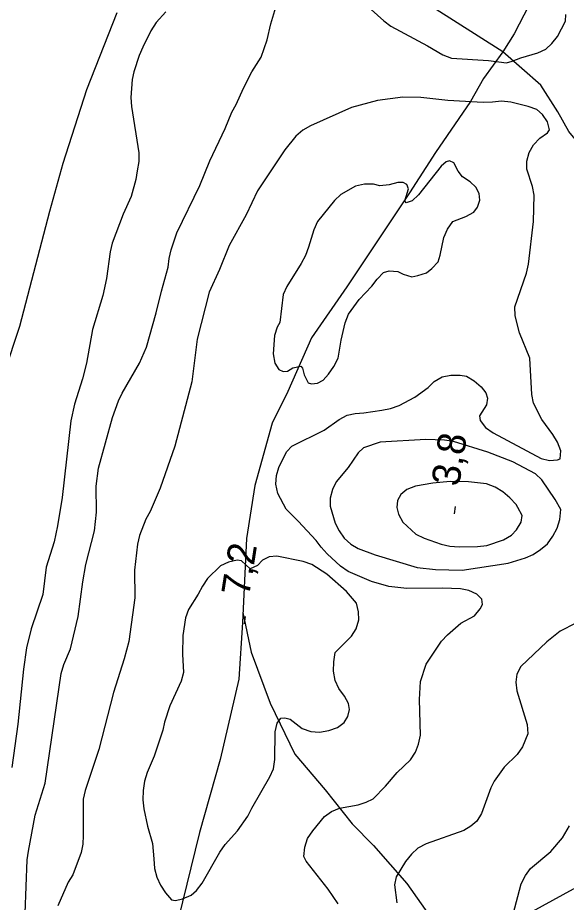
# Model space of a CAD drawing. Extents: x 282461 to 284471, y 5554090 to 5557646.
# Drawn here: x 282768 to 282826.3, y 5554895.5 to 5554989.5 of the extents above; entities that cross this region are included whole.
import ezdxf

# ---------------------------------------------------------------- set-up
doc = ezdxf.new("R2010")
doc.units = 0
for name, color, linetype in [('Niveau 1', 7, 'Continuous'), ('Niveau 2', 7, 'Continuous'), ('Niveau 22', 7, 'Continuous'), ('Niveau 3', 7, 'Continuous')]:
    doc.layers.add(name, color=color, linetype=linetype)

msp = doc.modelspace()

# ---------------------------------------------------------------- linework, layer by layer
at = {"layer": 'Niveau 1'}
for points in [[(282768.74, 5554894.3), (282768.95, 5554899.96), (282769.11, 5554900.89), (282769.82, 5554904.71), (282770.87, 5554908.12), (282772.57, 5554919.8), (282772.85, 5554920.73), (282773.57, 5554922.41), (282774.4, 5554925.83), (282774.87, 5554929.53), (282775.19, 5554931.38), (282776.13, 5554934.97), (282776.33, 5554936.93), (282776.3, 5554939.7), (282776.56, 5554941.61), (282778.05, 5554947), (282778.67, 5554948.79), (282779.06, 5554949.61), (282780.92, 5554952.8), (282781.65, 5554954.48), (282782.7, 5554958.13), (282783.25, 5554960.45), (282783.97, 5554962.99), (282784.07, 5554963.92), (282784.29, 5554964.85), (282784.9, 5554966.64), (282787.32, 5554971.69), (282788.39, 5554974.3), (282790.02, 5554977.72), (282790.74, 5554979.46), (282791.2, 5554980.27), (282791.98, 5554982.01), (282792.88, 5554983.76), (282793.85, 5554985.32), (282794.51, 5554987.18), (282794.9, 5554988.86), (282796.28, 5554993.49)], [(282805.55, 5554990.4), (282806.9, 5554989.2), (282807.65, 5554988.63), (282811.55, 5554986.53), (282813.17, 5554985.56), (282814.1, 5554985.22), (282818.03, 5554984.97), (282819.94, 5554984.7), (282820.57, 5554984.88), (282821.49, 5554985.24), (282823.27, 5554985.77), (282824.13, 5554986.18), (282824.76, 5554986.77), (282825.39, 5554987.53), (282826.23, 5554989.15), (282826.28, 5554989.84)], [(282825.13, 5554938.3), (282823.72, 5554940.37), (282823.02, 5554941), (282820.64, 5554942.3), (282817.97, 5554943.32), (282814.32, 5554944.44), (282813.34, 5554944.61), (282811.38, 5554944.65), (282806.53, 5554944.37), (282804.75, 5554943.78), (282804.18, 5554943.25), (282803.1, 5554941.68), (282801.85, 5554940.17), (282801.46, 5554939.36), (282801.18, 5554938.43), (282801.19, 5554937.56), (282801.74, 5554935.78), (282802.15, 5554934.97), (282802.68, 5554934.17), (282803.38, 5554933.54), (282804.19, 5554933.09), (282805.99, 5554932.41), (282810.45, 5554931.06), (282812.41, 5554930.85), (282815.24, 5554930.76), (282820.14, 5554931.5), (282821.98, 5554932.09), (282822.78, 5554932.45), (282823.58, 5554932.97), (282824.33, 5554933.56), (282824.89, 5554934.37), (282825.34, 5554935.24), (282825.62, 5554936.17), (282825.72, 5554937.21), (282825.13, 5554938.3)], [(282827.32, 5554925.15), (282825.65, 5554924.27), (282824.23, 5554923.16), (282821.49, 5554920.53), (282821.04, 5554919.72), (282820.93, 5554918.85), (282821.06, 5554917.93), (282822.14, 5554914.36), (282822.21, 5554913.38), (282821.65, 5554911.99), (282821.09, 5554911.17), (282819.72, 5554909.83), (282818.64, 5554908.32), (282818.3, 5554907.62), (282817.3, 5554904.9), (282816.79, 5554904.09), (282816.16, 5554903.56), (282815.42, 5554903.09), (282811.39, 5554901.67), (282810.53, 5554901.2), (282809.85, 5554900.56), (282809.22, 5554899.8), (282808.21, 5554898.18), (282808.04, 5554897.31), (282808.3, 5554895.41)]]:
    msp.add_lwpolyline(points, dxfattribs=at)
at = {"layer": 'Niveau 2'}
for points in [[(282783.7, 5554990.15), (282782.67, 5554988.99), (282782.11, 5554988.12), (282781.26, 5554986.37), (282780.87, 5554985.5), (282780.32, 5554983.76), (282780.15, 5554982.95), (282780, 5554981.04)], [(282780, 5554981.04), (282780.07, 5554980.06), (282780.83, 5554975.16), (282780.84, 5554974.23), (282780.68, 5554973.25), (282780.52, 5554972.32), (282780.02, 5554970.52), (282779.18, 5554968.61), (282778, 5554965.53), (282777.78, 5554964.61), (282777.42, 5554961.77), (282777.03, 5554959.98), (282775.92, 5554956.38), (282775.28, 5554952.79), (282774.84, 5554951.11), (282774, 5554948.44), (282773.62, 5554946.65), (282772.68, 5554938.49), (282772.2, 5554935.48), (282771.82, 5554933.8), (282770.99, 5554931.08), (282770.62, 5554928.18), (282769.4, 5554924.53), (282768.9, 5554922.5), (282768.58, 5554920.25), (282767.96, 5554914.4), (282767.33, 5554909.78)], [(282823.71, 5554946.8), (282822.83, 5554948.52), (282822.64, 5554949.45), (282822.42, 5554953.31), (282821.35, 5554956.01), (282820.87, 5554957.8), (282820.85, 5554958.78), (282822.08, 5554962.37), (282822.3, 5554963.3), (282822.82, 5554967.86), (282822.9, 5554970.63), (282822.71, 5554971.56), (282822.11, 5554973.4), (282822.1, 5554974.26), (282822.38, 5554975.19), (282822.83, 5554976), (282823.51, 5554976.7), (282824.31, 5554977.29), (282824.54, 5554977.58), (282824.3, 5554978.44), (282823.77, 5554979.24), (282823.19, 5554979.76), (282822.26, 5554980.09), (282820.41, 5554980.54), (282819.43, 5554980.65), (282818.45, 5554980.52), (282817.47, 5554980.51), (282813.72, 5554980.71), (282810.83, 5554981.03), (282808.93, 5554981.07), (282806.22, 5554980.7), (282803.46, 5554979.98), (282799.11, 5554978.03), (282798.3, 5554977.56), (282797.56, 5554976.92), (282796.37, 5554975.47), (282793.48, 5554971.11), (282792.25, 5554968.56), (282790.44, 5554965.31), (282789.44, 5554962.76), (282788.31, 5554960.33), (282787.05, 5554955.35), (282786.47, 5554950.79), (282784.66, 5554943.96), (282783.1, 5554939.5), (282782.03, 5554937.01), (282781.58, 5554936.2), (282780.91, 5554934.46), (282780.69, 5554933.54), (282780.38, 5554930.77), (282780.42, 5554927.82), (282779.79, 5554923.2), (282779.29, 5554921.35), (282778.13, 5554917.76), (282776.59, 5554911.69), (282775.14, 5554907.35), (282774.92, 5554906.42), (282774.92, 5554902.56), (282774.87, 5554901.63), (282774.71, 5554900.76), (282773.81, 5554898.39), (282773.31, 5554897.58), (282772.24, 5554895.09)], [(282795.83, 5554957.12), (282795.55, 5554956.6), (282795.27, 5554955.73), (282795.12, 5554953.77), (282795.31, 5554952.79), (282795.72, 5554952.1), (282796.18, 5554951.88), (282796.64, 5554951.94), (282797.21, 5554952.29), (282798.08, 5554952.47), (282798.25, 5554952.24), (282798.43, 5554951.55), (282798.85, 5554950.69), (282799.2, 5554950.58), (282799.83, 5554950.64), (282800.46, 5554950.99), (282801.03, 5554951.63), (282801.59, 5554952.44), (282802.04, 5554953.31), (282802.36, 5554955.22), (282802.8, 5554957.07), (282803.14, 5554958), (282804.27, 5554959.56), (282805.63, 5554960.96), (282806.2, 5554961.71), (282806.88, 5554962.41), (282807.46, 5554962.59), (282808.38, 5554962.54), (282808.96, 5554962.26), (282809.88, 5554961.98), (282810.52, 5554962.1), (282811.43, 5554962.4), (282812, 5554962.86), (282812.69, 5554963.56), (282812.91, 5554964.26), (282813.29, 5554966.16), (282813.68, 5554967.03), (282814.25, 5554967.84), (282815.62, 5554968.38), (282816.48, 5554968.85), (282816.88, 5554969.37), (282817.1, 5554970.12), (282817.03, 5554970.81), (282816.68, 5554971.5), (282816.1, 5554972.07), (282815.28, 5554972.58), (282814.81, 5554973.21), (282814.34, 5554974.07), (282813.88, 5554974.3), (282813.53, 5554974.18), (282813.02, 5554973.72), (282810.58, 5554970.69), (282809.9, 5554970.05), (282809.27, 5554969.82), (282809.15, 5554970.05), (282809.54, 5554971.32), (282809.36, 5554971.78), (282808.95, 5554972.01), (282808.38, 5554972), (282807.46, 5554971.76), (282806.48, 5554971.64), (282805.79, 5554971.8), (282804.86, 5554971.8), (282803.89, 5554971.61), (282802.34, 5554970.73), (282801.66, 5554970.09), (282799.84, 5554967.83), (282799.45, 5554966.96), (282798.9, 5554965.11), (282798.56, 5554964.24), (282798.11, 5554963.37), (282796.59, 5554960.93), (282796.2, 5554960.07), (282795.83, 5554957.12)], [(282802.04, 5554895.3), (282800.99, 5554896.84), (282798.64, 5554899.82), (282798.41, 5554900.34), (282798.51, 5554901.32), (282798.78, 5554902.25), (282799.35, 5554903.06), (282800.6, 5554904.57), (282801.34, 5554905.1), (282802.2, 5554905.45), (282804.16, 5554905.82), (282805.02, 5554906.11), (282805.77, 5554906.47), (282807.08, 5554907.81), (282808.33, 5554909.26), (282809.75, 5554910.6), (282810.26, 5554911.41), (282810.59, 5554912.28), (282810.81, 5554913.21), (282810.71, 5554917.01), (282810.8, 5554918.92), (282811.41, 5554920.77), (282813.05, 5554923.21), (282813.68, 5554923.91), (282815.1, 5554925.13), (282816.54, 5554925.9), (282817.16, 5554926.65), (282817.39, 5554927.12), (282817.32, 5554927.69), (282816.8, 5554928.21), (282815.93, 5554928.61), (282815.06, 5554928.77), (282813.15, 5554928.87), (282809.35, 5554928.83), (282807.44, 5554929.05), (282805.59, 5554929.55), (282803.1, 5554930.62), (282802.29, 5554931.19), (282800.89, 5554932.51), (282800.24, 5554933.2), (282799.71, 5554933.94), (282797.79, 5554936), (282796.5, 5554937.26), (282795.62, 5554938.93), (282795.43, 5554939.9), (282795.48, 5554940.83), (282795.75, 5554941.7), (282796.15, 5554942.57), (282796.6, 5554943.38), (282797.11, 5554943.96), (282800.55, 5554945.67), (282802.15, 5554946.78), (282803.01, 5554947.25), (282803.87, 5554947.43), (282804.79, 5554947.49), (282806.69, 5554947.8), (282807.61, 5554947.98), (282808.53, 5554948.28), (282810.19, 5554949.16), (282811.62, 5554950.21), (282812.25, 5554950.85), (282813.11, 5554951.32), (282814.03, 5554951.5), (282815.01, 5554951.51), (282815.7, 5554951.4), (282816.51, 5554950.89), (282817.27, 5554950.26), (282817.74, 5554949.63), (282817.92, 5554949.06), (282817.81, 5554948.36), (282817.08, 5554947.2), (282817.14, 5554946.68), (282817.73, 5554945.94), (282818.54, 5554945.37), (282823.65, 5554942.64), (282824.52, 5554942.42), (282825.38, 5554942.49), (282825.67, 5554942.6), (282825.72, 5554943.47), (282825.36, 5554944.39), (282824.89, 5554945.2), (282823.71, 5554946.8)], [(282821.15, 5554937.43), (282820.97, 5554937.77), (282820.32, 5554938.46), (282819.57, 5554939.09), (282818.75, 5554939.6), (282817.82, 5554939.94), (282815.91, 5554940.16), (282813.95, 5554940.2), (282812.1, 5554940.01), (282810.26, 5554939.7), (282809.34, 5554939.35), (282808.71, 5554938.82), (282808.37, 5554938.18), (282808.27, 5554937.43), (282808.45, 5554936.74), (282808.92, 5554935.87), (282810.32, 5554934.61), (282811.19, 5554934.16), (282812.99, 5554933.54), (282813.92, 5554933.32), (282814.9, 5554933.27), (282816.87, 5554933.29), (282817.85, 5554933.41), (282819.63, 5554934), (282820.49, 5554934.48), (282821, 5554935.06), (282821.51, 5554935.87), (282821.62, 5554936.57), (282821.15, 5554937.43)], [(282782.43, 5554900.08), (282782.5, 5554899.05), (282782.74, 5554898.13), (282783.16, 5554897.26), (282783.69, 5554896.46), (282784.33, 5554895.72), (282784.73, 5554895.66), (282785.48, 5554895.84), (282786.4, 5554896.2), (282786.97, 5554896.72), (282787.59, 5554897.48), (282789.45, 5554900.78), (282790.01, 5554901.59), (282791.32, 5554903.05), (282792.45, 5554904.61), (282792.85, 5554905.48), (282794.76, 5554908.79), (282795.16, 5554909.65), (282795.32, 5554910.64), (282795.34, 5554913.58), (282795.56, 5554914.5), (282795.95, 5554915.02), (282796.36, 5554915.08), (282796.93, 5554914.92), (282798.21, 5554913.95), (282799.14, 5554913.61), (282800.06, 5554913.56), (282801.04, 5554913.74), (282801.96, 5554914.04), (282802.7, 5554914.57), (282803.09, 5554915.2), (282803.26, 5554915.95), (282803.13, 5554916.59), (282802.72, 5554917.39), (282802.13, 5554918.19), (282801.72, 5554919.05), (282801.54, 5554920.03), (282801.58, 5554921.01), (282801.74, 5554922), (282803.45, 5554923.74), (282803.96, 5554924.55), (282804.23, 5554925.48), (282804.22, 5554926.34), (282803.98, 5554927.26), (282802.93, 5554928.52), (282800.83, 5554930.35), (282799.26, 5554931.37), (282798.34, 5554931.71), (282795.51, 5554932.26), (282794.7, 5554932.2), (282794.01, 5554931.84), (282793.45, 5554931.26), (282792.7, 5554930.91), (282791.77, 5554931.77), (282791.31, 5554931.82), (282790.39, 5554931.64), (282789.53, 5554931.23), (282788.16, 5554929.89), (282787.6, 5554929.08), (282787.15, 5554928.21), (282786.13, 5554926.58), (282785.8, 5554925.72), (282785.53, 5554923.81), (282785.5, 5554921.85), (282785.58, 5554919.89), (282785.36, 5554918.96), (282784.13, 5554916.36), (282783.57, 5554914.62), (282783.41, 5554913.76), (282782.47, 5554910.98), (282781.74, 5554909.25), (282781.46, 5554908.32), (282781.3, 5554907.34), (282781.26, 5554906.36), (282781.38, 5554905.38), (282781.75, 5554903.54), (282782.29, 5554901.7), (282782.43, 5554900.08)], [(282820.65, 5554894.18), (282821.53, 5554897.43), (282821.98, 5554898.3), (282822.49, 5554899.06), (282824.66, 5554900.87), (282825.92, 5554902.32), (282826.65, 5554903.6)]]:
    msp.add_lwpolyline(points, dxfattribs=at)
at = {"layer": 'Niveau 22'}
for points in [[(282900.56, 5554916.22), (282898.03, 5554916.45), (282894.89, 5554917.47), (282887.5, 5554921.36), (282882.7, 5554925.6), (282873.79, 5554934.21), (282869.34, 5554938.23), (282863.61, 5554942.81), (282861.13, 5554944.4), (282856.73, 5554948.67), (282852.55, 5554952.35), (282848.19, 5554955.68), (282844.29, 5554958.9), (282840.86, 5554962), (282834.82, 5554967.63), (282831.24, 5554971.19), (282828.27, 5554975.35), (282826.59, 5554977.42), (282825.41, 5554979.49), (282823.6, 5554982.35), (282819.57, 5554985.87), (282809.46, 5554992.33)], [(282822.34, 5554990.83), (282820.76, 5554987.81), (282819.57, 5554985.87), (282817.52, 5554983.05), (282816.13, 5554980.62), (282812.41, 5554975.18), (282809.63, 5554970.89), (282802.96, 5554960.91), (282799.2, 5554955.47), (282796.68, 5554949.77), (282795.02, 5554946.4), (282793.17, 5554939.79), (282792.29, 5554934.14), (282791.86, 5554925.19), (282791.47, 5554919.19), (282789.5, 5554910.64), (282787.3, 5554902.89), (282785.02, 5554893.63)], [(282778.5, 5554990.05), (282775.27, 5554981.86), (282772.77, 5554974.03), (282771.34, 5554968.92), (282768.14, 5554956.69), (282766.53, 5554951.76)], [(282791.91, 5554926.27), (282792.79, 5554922.04), (282794.81, 5554916.63), (282797.44, 5554911.22), (282800.66, 5554907.4), (282803.53, 5554903.81), (282805.79, 5554901.5), (282809.36, 5554897.44), (282822.57, 5554878.7)], [(282881.88, 5554912.2), (282879.07, 5554910.49), (282875.28, 5554908.69), (282869.28, 5554906.73), (282863.91, 5554905.56), (282860.29, 5554904.54), (282848.72, 5554902.4), (282842.21, 5554901.34), (282837.94, 5554900.22), (282827.03, 5554896.85), (282822.64, 5554894.43)]]:
    msp.add_lwpolyline(points, dxfattribs=at)
at = {"layer": 'Niveau 3'}
for p, q in [((282814.42, 5554936.76), (282814.54, 5554937.55)), ((282792.08, 5554925.05), (282792.2, 5554925.84))]:
    msp.add_line(p, q, dxfattribs=at)

# ---------------------------------------------------------------- texts
for s, p in [('3,8  ', (282814.9, 5554939.6)), ('7,2  ', (282792.56, 5554927.89))]:
    msp.add_text(s, height=3, rotation=81.09575, dxfattribs=at).set_placement(p)

doc.saveas('drawing.dxf')
